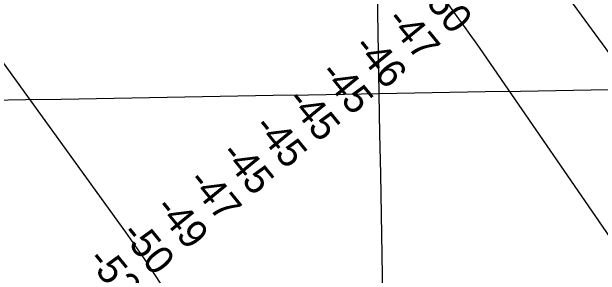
# Model space of a CAD drawing. Extents: x 3892998 to 3931244, y 278583 to 304547.
# Drawn here: x 3912238 to 3913620, y 289921 to 290539 of the extents above; entities that cross this region are included whole.
import ezdxf

# ---------------------------------------------------------------- set-up
doc = ezdxf.new("R2010")
doc.units = 0
for name, color, linetype in [('V-GRID-MAJR', 7, 'Continuous'), ('V-RIVR-EDGE', 7, 'Continuous'), ('V-RIVR-RANG', 7, 'Continuous'), ('V-TOPO-MAJR', 7, 'Continuous')]:
    doc.layers.add(name, color=color, linetype=linetype)

msp = doc.modelspace()

# ---------------------------------------------------------------- linework, layer by layer
at = {"layer": 'V-GRID-MAJR'}
for points in [[(3913205.7, 284291.2), (3913100.9, 290347.6), (3912996, 296407.6), (3912891.1, 302467.5), (3912891, 302471)], [(3897162.9, 290075.2), (3902475.5, 290165.2), (3907788.2, 290256), (3913100.9, 290347.6), (3918413.5, 290440), (3923726.1, 290533.1), (3929038.7, 290627)]]:
    msp.add_spline(points, degree=3, dxfattribs=at)
at = {"layer": 'V-RIVR-EDGE'}
msp.add_spline([(3909865.8, 290928.2), (3909862.6, 290923.1), (3909860.7, 290922.6), (3909860.7, 290920.7), (3909870.3, 290905.1), (3909881.9, 290877.9), (3909893.5, 290856.5), (3909906.1, 290843.8), (3909921.6, 290817.6), (3909937.1, 290794.7), (3909948.2, 290777.2), (3909977.7, 290734.4), (3910003.4, 290694.5), (3910040.6, 290645.9), (3910078.4, 290595.3), (3910114.2, 290544.2), (3910151.5, 290493.6), (3910182, 290444.5), (3910200.8, 290413.3), (3910226.9, 290368.6), (3910256.9, 290323.8), (3910278.7, 290289.3), (3910307.7, 290250.4), (3910325.2, 290226.5), (3910363.9, 290167.2), (3910391.4, 290124.9), (3910427.7, 290068.9), (3910449.5, 290036.8), (3910504.2, 289956.6), (3910522.1, 289926.9), (3910550.1, 289879.7), (3910562.2, 289857.4), (3910573.3, 289842.3), (3910610.6, 289806.7), (3910620.8, 289794.1), (3910623.2, 289780), (3910634.8, 289764.4), (3910664.8, 289724), (3910692.4, 289689.5), (3910710.8, 289668.1), (3910721, 289660.3), (3910770.9, 289605.3), (3910782.5, 289588.7), (3910807.7, 289548.4), (3910835.7, 289503.6), (3910862.8, 289470), (3910892.3, 289425.8), (3910920.4, 289383.5), (3910948, 289342.6), (3910968.8, 289304.7), (3911000.2, 289260.9), (3911019.6, 289231.7), (3911055.9, 289191.3), (3911085.5, 289159.7), (3911118.9, 289116.8), (3911139.2, 289091.1), (3911161, 289062.3), (3911184.2, 289025.9), (3911223.4, 288981.6), (3911281.5, 288916.4), (3911313, 288876.9), (3911328.5, 288859.4), (3911346.4, 288837.5), (3911371.6, 288801), (3911404.5, 288751.9), (3911426.7, 288715.4), (3911446.6, 288687.7), (3911479, 288646.8), (3911529.4, 288582.1), (3911550.6, 288552.9), (3911609.2, 288468.3), (3911644.5, 288421.1), (3911677, 288378.8), (3911701.2, 288348.1), (3911741.4, 288303.8), (3911770.9, 288264.9), (3911788.8, 288235.7), (3911834.3, 288164.7), (3911857.5, 288130.2), (3911884.6, 288092.7), (3911915.6, 288045.5), (3911921.9, 288035.8), (3911928.6, 288029.9), (3911972.6, 287945.8), (3911992.9, 287906.4), (3912000.6, 287887), (3912014.7, 287866.5), (3912026.8, 287848.1), (3912066.4, 287785.3), (3912084.8, 287750.8), (3912094.5, 287732.8), (3912094.9, 287726), (3912096.8, 287711.4), (3912096.3, 287704.6), (3912095.4, 287700.3), (3912088.6, 287695.9), (3912085.6, 287696.9), (3912073, 287702.3), (3912062.4, 287706.2), (3912054.1, 287706.2), (3912051.2, 287704.3), (3912049.2, 287697.9), (3912054, 287685.8), (3912068.6, 287663.9), (3912113.1, 287586.6), (3912136.7, 287540.9), (3912153.7, 287513.6), (3912163.8, 287503.9), (3912187.6, 287479.6), (3912207.4, 287453.3), (3912216.1, 287446), (3912226.8, 287436.2), (3912240.8, 287416.8), (3912253.4, 287397.8), (3912271.3, 287366.2), (3912283.9, 287341.4), (3912284.8, 287339), (3912290.2, 287338), (3912303.8, 287344.3), (3912317.4, 287350.5), (3912319.8, 287350.5), (3912322.7, 287350.5), (3912327.6, 287345.7), (3912328.5, 287338.4), (3912335.8, 287321.4), (3912348.4, 287300), (3912369.2, 287275.1), (3912380.3, 287265.4), (3912402.1, 287253.2), (3912416.7, 287243.5), (3912434.2, 287238.1), (3912456.9, 287220), (3912481.6, 287183.6), (3912501.9, 287148.1), (3912512.6, 287124.7), (3912531.4, 287085.8), (3912550.3, 287059.6), (3912569.6, 287034.3), (3912593.3, 286996.8), (3912613.7, 286968.1), (3912632, 286936.5), (3912645.1, 286912.7), (3912660.6, 286888.8), (3912675.1, 286867.4), (3912698.3, 286835.3), (3912720.1, 286784.8), (3912737, 286747.8), (3912742.3, 286740), (3912755.3, 286715.2), (3912761.6, 286696.8), (3912774.1, 286660.3), (3912779.9, 286635.5), (3912793.4, 286585.5), (3912797.2, 286569.4), (3912804, 286543.7), (3912804.4, 286532)], degree=3, dxfattribs=at)
at = {"layer": 'V-TOPO-MAJR'}
for points in [[(3912484.1, 291702), (3912531, 291634.5), (3912578, 291567), (3912624.9, 291499.6), (3912816.6, 291223.4), (3912829.1, 291205.4), (3912841.6, 291187.2), (3912853.9, 291169), (3912866.1, 291150.8), (3913227, 290610.6), (3913234.3, 290599.6), (3913241.7, 290588.5), (3913249, 290577.5), (3913256.4, 290566.4), (3913263.8, 290555.4), (3913271.3, 290544.5), (3913279, 290533.7), (3913286.9, 290522.9), (3913293.4, 290514.1), (3913304.6, 290499), (3913315.6, 290483.8), (3913326.4, 290468.5), (3913337.2, 290453.1), (3913674.7, 289963.4)], [(3913648.9, 290432), (3913616.6, 290475.6), (3913584.5, 290519.4), (3913552.7, 290563.4)], [(3912591.4, 289895.8), (3912570.6, 289927.8), (3912549.4, 289959.5), (3912527.7, 289990.9), (3912505.6, 290022), (3912156.4, 290504)]]:
    msp.add_lwpolyline(points, dxfattribs=at)

# ---------------------------------------------------------------- texts
at = {"layer": 'V-RIVR-RANG'}
for s, p in [('-50', (3913190.7, 290583.6)), ('-47', (3913114.7, 290518.6)), ('-46', (3913037.1, 290455.4)), ('-45', (3912958.5, 290393.7)), ('-45', (3912880.8, 290330.7)), ('-45', (3912803.1, 290267.8)), ('-45', (3912725.4, 290204.8)), ('-47', (3912648.5, 290140.8)), ('-49', (3912571.2, 290077.4)), ('-50', (3912491.5, 290016.9)), ('-52', (3912412.6, 289955.4))]:
    msp.add_text(s, height=67, rotation=309.1656, dxfattribs=at).set_placement(p)

doc.saveas('drawing.dxf')
